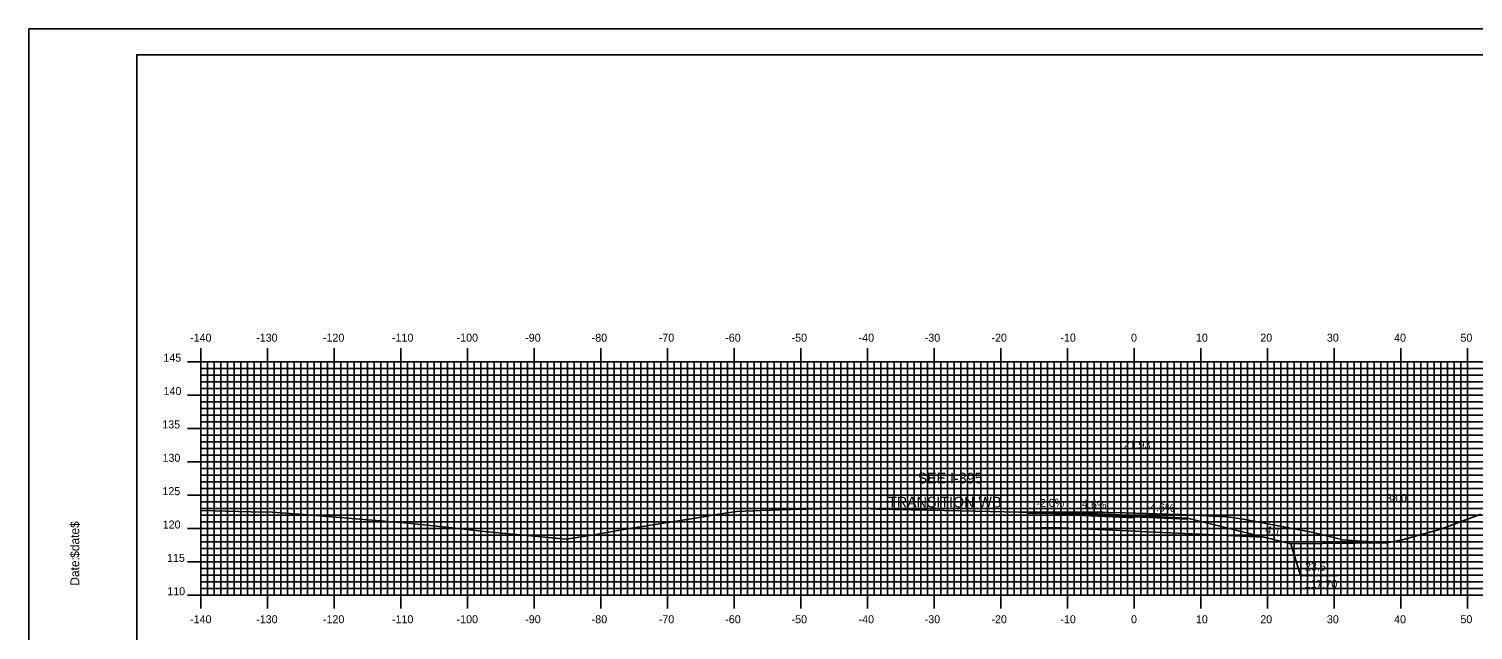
# Model space of a CAD drawing. Extents: x 853328 to 853671, y 364661 to 364881.
# Drawn here: x 853327.5 to 853544.1, y 364791.1 to 364881.3 of the extents above; entities that cross this region are included whole.
import ezdxf

# ---------------------------------------------------------------- set-up
doc = ezdxf.new("R2010")
doc.units = 0
for name, color, linetype in [('ANNOTATION', 7, 'Continuous'), ('BORDER', 7, 'Continuous'), ('D_Roadway_Centerline_Text', 7, 'Continuous'), ('D_Roadway_Edge_Shoulder', 7, 'Continuous'), ('D_Roadway_Edge_TW', 7, 'Continuous'), ('D_Roadway_Pavement', 7, 'Continuous'), ('D_Roadway_SubGrade', 7, 'Continuous'), ('D_Text_Standard', 7, 'Continuous'), ('H_V ANNOTATION', 7, 'Continuous'), ('M_Roadway_Centerline', 7, 'Continuous'), ('MAJOR', 7, 'Continuous'), ('MINOR', 7, 'Continuous'), ('PLOT BOUNDARY', 7, 'Continuous'), ('S_Roadway_Centerline', 7, 'Continuous')]:
    doc.layers.add(name, color=color, linetype=linetype)

msp = doc.modelspace()

# ---------------------------------------------------------------- linework, layer by layer
at = {"layer": 'ANNOTATION'}
for points in [[(853512.79, 364805.07), (853516.79, 364804.07), (853531.25, 364804.2)], [(853523.9, 364799.34), (853518.21, 364799.34), (853516.79, 364804.07)]]:
    msp.add_lwpolyline(points, dxfattribs=at)
at = {"layer": 'BORDER'}
msp.add_lwpolyline([(853343.69, 364667.37), (853663.69, 364667.37), (853663.69, 364877.37), (853343.69, 364877.37)], close=True, dxfattribs=at)
at = {"layer": 'D_Roadway_Edge_Shoulder'}
for points in [[(853481.29, 364808.86), (853477.29, 364808.78), (853477.29, 364808.61), (853481.29, 364808.68)], [(853493.29, 364808.31), (853501.29, 364807.94), (853501.29, 364807.77), (853493.29, 364808.13)]]:
    msp.add_lwpolyline(points, close=True, dxfattribs=at)
at = {"layer": 'D_Roadway_Edge_TW'}
msp.add_lwpolyline([(853481.29, 364808.86), (853493.29, 364808.31), (853493.29, 364808.13), (853481.29, 364808.68)], close=True, dxfattribs=at)
at = {"layer": 'D_Roadway_Pavement'}
msp.add_lwpolyline([(853481.29, 364808.68), (853493.29, 364808.13), (853493.29, 364807.96), (853481.29, 364808.51)], close=True, dxfattribs=at)
for points in [[(853481.29, 364808.68), (853481.29, 364808.51)], [(853493.29, 364808.13), (853493.29, 364807.96)], [(853493.29, 364808.13), (853493.29, 364807.96)]]:
    msp.add_lwpolyline(points, dxfattribs=at)
at = {"layer": 'D_Roadway_SubGrade'}
msp.add_line((853477.29, 364806.43), (853477.29, 364816.24), dxfattribs=at)
for points in [[(853481.29, 364806.51), (853477.29, 364806.43), (853477.29, 364808.78), (853477.29, 364808.61), (853481.29, 364808.68), (853481.29, 364808.51)], [(853481.29, 364808.51), (853493.29, 364807.96), (853493.29, 364805.96), (853481.29, 364806.51)], [(853493.29, 364807.96), (853493.29, 364808.13), (853501.29, 364807.77), (853501.29, 364807.94), (853512.79, 364805.07), (853493.29, 364805.96)]]:
    msp.add_lwpolyline(points, close=True, dxfattribs=at)
at = {"layer": 'MAJOR'}
for p, q in [((853353.29, 364833.38), (853353.29, 364831.37)), ((853363.29, 364833.38), (853363.29, 364831.37)), ((853373.29, 364833.38), (853373.29, 364831.37)), ((853383.29, 364833.38), (853383.29, 364831.37)), ((853393.29, 364833.38), (853393.29, 364831.37)), ((853403.29, 364833.38), (853403.29, 364831.37)), ((853413.29, 364833.38), (853413.29, 364831.37)), ((853423.29, 364833.38), (853423.29, 364831.37)), ((853433.29, 364833.38), (853433.29, 364831.37)), ((853443.29, 364833.38), (853443.29, 364831.37)), ((853453.29, 364833.38), (853453.29, 364831.37)), ((853463.29, 364833.38), (853463.29, 364831.37)), ((853473.29, 364833.38), (853473.29, 364831.37)), ((853483.29, 364833.38), (853483.29, 364831.37)), ((853493.29, 364833.38), (853493.29, 364831.37)), ((853503.29, 364833.38), (853503.29, 364831.37)), ((853513.29, 364833.38), (853513.29, 364831.37)), ((853523.29, 364833.38), (853523.29, 364831.37)), ((853533.29, 364833.38), (853533.29, 364831.37)), ((853543.29, 364833.38), (853543.29, 364831.37)), ((853351.29, 364831.37), (853353.29, 364831.37)), ((853353.29, 364831.37), (853633.29, 364831.37)), ((853353.29, 364796.37), (853353.29, 364831.37)), ((853353.29, 364796.37), (853353.29, 364831.37)), ((853353.29, 364831.37), (853633.29, 364831.37)), ((853363.29, 364796.37), (853363.29, 364831.37)), ((853373.29, 364796.37), (853373.29, 364831.37)), ((853383.29, 364796.37), (853383.29, 364831.37)), ((853393.29, 364796.37), (853393.29, 364831.37)), ((853403.29, 364796.37), (853403.29, 364831.37)), ((853413.29, 364796.37), (853413.29, 364831.37)), ((853423.29, 364796.37), (853423.29, 364831.37)), ((853433.29, 364796.37), (853433.29, 364831.37)), ((853443.29, 364796.37), (853443.29, 364831.37)), ((853453.29, 364796.37), (853453.29, 364831.37)), ((853463.29, 364796.37), (853463.29, 364831.37)), ((853473.29, 364796.37), (853473.29, 364831.37)), ((853483.29, 364796.37), (853483.29, 364831.37)), ((853493.29, 364796.37), (853493.29, 364831.37)), ((853503.29, 364796.37), (853503.29, 364831.37)), ((853513.29, 364796.37), (853513.29, 364831.37)), ((853523.29, 364796.37), (853523.29, 364831.37)), ((853533.29, 364796.37), (853533.29, 364831.37)), ((853543.29, 364796.37), (853543.29, 364831.37)), ((853351.29, 364826.37), (853353.29, 364826.37)), ((853353.29, 364826.37), (853633.29, 364826.37)), ((853351.29, 364821.37), (853353.29, 364821.37)), ((853353.29, 364821.37), (853633.29, 364821.37)), ((853351.29, 364816.37), (853353.29, 364816.37)), ((853353.29, 364816.37), (853633.29, 364816.37)), ((853351.29, 364811.37), (853353.29, 364811.37)), ((853353.29, 364811.37), (853633.29, 364811.37)), ((853351.29, 364806.37), (853353.29, 364806.37)), ((853353.29, 364806.37), (853633.29, 364806.37)), ((853351.29, 364801.37), (853353.29, 364801.37)), ((853353.29, 364801.37), (853633.29, 364801.37)), ((853351.29, 364796.37), (853353.29, 364796.37)), ((853353.29, 364796.37), (853633.29, 364796.37)), ((853353.29, 364796.37), (853633.29, 364796.37)), ((853353.29, 364794.37), (853353.29, 364796.37)), ((853363.29, 364794.37), (853363.29, 364796.37)), ((853373.29, 364794.37), (853373.29, 364796.37)), ((853383.29, 364794.37), (853383.29, 364796.37)), ((853393.29, 364794.37), (853393.29, 364796.37)), ((853403.29, 364794.37), (853403.29, 364796.37)), ((853413.29, 364794.37), (853413.29, 364796.37)), ((853423.29, 364794.37), (853423.29, 364796.37)), ((853433.29, 364794.37), (853433.29, 364796.37)), ((853443.29, 364794.37), (853443.29, 364796.37)), ((853453.29, 364794.37), (853453.29, 364796.37)), ((853463.29, 364794.37), (853463.29, 364796.37)), ((853473.29, 364794.37), (853473.29, 364796.37)), ((853483.29, 364794.37), (853483.29, 364796.37)), ((853493.29, 364794.37), (853493.29, 364796.37)), ((853503.29, 364794.37), (853503.29, 364796.37)), ((853513.29, 364794.37), (853513.29, 364796.37)), ((853523.29, 364794.37), (853523.29, 364796.37)), ((853533.29, 364794.37), (853533.29, 364796.37)), ((853543.29, 364794.37), (853543.29, 364796.37))]:
    msp.add_line(p, q, dxfattribs=at)
at = {"layer": 'MINOR'}
for p, q in [((853353.29, 364830.37), (853633.29, 364830.37)), ((853353.29, 364830.37), (853355.3, 364830.37)), ((853354.29, 364796.37), (853354.29, 364831.37)), ((853355.29, 364796.37), (853355.29, 364831.37)), ((853356.29, 364796.37), (853356.29, 364831.37)), ((853357.29, 364796.37), (853357.29, 364831.37)), ((853358.29, 364796.37), (853358.29, 364831.37)), ((853359.29, 364796.37), (853359.29, 364831.37)), ((853360.29, 364796.37), (853360.29, 364831.37)), ((853361.29, 364796.37), (853361.29, 364831.37)), ((853362.29, 364796.37), (853362.29, 364831.37)), ((853364.29, 364796.37), (853364.29, 364831.37)), ((853365.29, 364796.37), (853365.29, 364831.37)), ((853366.29, 364796.37), (853366.29, 364831.37)), ((853367.29, 364796.37), (853367.29, 364831.37)), ((853368.29, 364796.37), (853368.29, 364831.37)), ((853369.29, 364796.37), (853369.29, 364831.37)), ((853370.29, 364796.37), (853370.29, 364831.37)), ((853371.29, 364796.37), (853371.29, 364831.37)), ((853372.29, 364796.37), (853372.29, 364831.37)), ((853374.29, 364796.37), (853374.29, 364831.37)), ((853375.29, 364796.37), (853375.29, 364831.37)), ((853376.29, 364796.37), (853376.29, 364831.37)), ((853377.29, 364796.37), (853377.29, 364831.37)), ((853378.29, 364796.37), (853378.29, 364831.37)), ((853379.29, 364796.37), (853379.29, 364831.37)), ((853380.29, 364796.37), (853380.29, 364831.37)), ((853381.29, 364796.37), (853381.29, 364831.37)), ((853382.29, 364796.37), (853382.29, 364831.37)), ((853384.29, 364796.37), (853384.29, 364831.37)), ((853385.29, 364796.37), (853385.29, 364831.37)), ((853386.29, 364796.37), (853386.29, 364831.37)), ((853387.29, 364796.37), (853387.29, 364831.37)), ((853388.29, 364796.37), (853388.29, 364831.37)), ((853389.29, 364796.37), (853389.29, 364831.37)), ((853390.29, 364796.37), (853390.29, 364831.37)), ((853391.29, 364796.37), (853391.29, 364831.37)), ((853392.29, 364796.37), (853392.29, 364831.37)), ((853394.29, 364796.37), (853394.29, 364831.37)), ((853395.29, 364796.37), (853395.29, 364831.37)), ((853396.29, 364796.37), (853396.29, 364831.37)), ((853397.29, 364796.37), (853397.29, 364831.37)), ((853398.29, 364796.37), (853398.29, 364831.37)), ((853399.29, 364796.37), (853399.29, 364831.37)), ((853400.29, 364796.37), (853400.29, 364831.37)), ((853401.29, 364796.37), (853401.29, 364831.37)), ((853402.29, 364796.37), (853402.29, 364831.37)), ((853404.29, 364796.37), (853404.29, 364831.37)), ((853405.29, 364796.37), (853405.29, 364831.37)), ((853406.29, 364796.37), (853406.29, 364831.37)), ((853407.29, 364796.37), (853407.29, 364831.37)), ((853408.29, 364796.37), (853408.29, 364831.37)), ((853409.29, 364796.37), (853409.29, 364831.37)), ((853410.29, 364796.37), (853410.29, 364831.37)), ((853411.29, 364796.37), (853411.29, 364831.37)), ((853412.29, 364796.37), (853412.29, 364831.37)), ((853414.29, 364796.37), (853414.29, 364831.37)), ((853415.29, 364796.37), (853415.29, 364831.37)), ((853416.29, 364796.37), (853416.29, 364831.37)), ((853417.29, 364796.37), (853417.29, 364831.37)), ((853418.29, 364796.37), (853418.29, 364831.37)), ((853419.29, 364796.37), (853419.29, 364831.37)), ((853420.29, 364796.37), (853420.29, 364831.37)), ((853421.29, 364796.37), (853421.29, 364831.37)), ((853422.29, 364796.37), (853422.29, 364831.37)), ((853424.29, 364796.37), (853424.29, 364831.37)), ((853425.29, 364796.37), (853425.29, 364831.37)), ((853426.29, 364796.37), (853426.29, 364831.37)), ((853427.29, 364796.37), (853427.29, 364831.37)), ((853428.29, 364796.37), (853428.29, 364831.37)), ((853429.29, 364796.37), (853429.29, 364831.37)), ((853430.29, 364796.37), (853430.29, 364831.37)), ((853431.29, 364796.37), (853431.29, 364831.37)), ((853432.29, 364796.37), (853432.29, 364831.37)), ((853434.29, 364796.37), (853434.29, 364831.37)), ((853435.29, 364796.37), (853435.29, 364831.37)), ((853436.29, 364796.37), (853436.29, 364831.37)), ((853437.29, 364796.37), (853437.29, 364831.37)), ((853438.29, 364796.37), (853438.29, 364831.37)), ((853439.29, 364796.37), (853439.29, 364831.37)), ((853440.29, 364796.37), (853440.29, 364831.37)), ((853441.29, 364796.37), (853441.29, 364831.37)), ((853442.29, 364796.37), (853442.29, 364831.37)), ((853444.29, 364796.37), (853444.29, 364831.37)), ((853445.29, 364796.37), (853445.29, 364831.37)), ((853446.29, 364796.37), (853446.29, 364831.37)), ((853447.29, 364796.37), (853447.29, 364831.37)), ((853448.29, 364796.37), (853448.29, 364831.37)), ((853449.29, 364796.37), (853449.29, 364831.37)), ((853450.29, 364796.37), (853450.29, 364831.37)), ((853451.29, 364796.37), (853451.29, 364831.37)), ((853452.29, 364796.37), (853452.29, 364831.37)), ((853454.29, 364796.37), (853454.29, 364831.37)), ((853455.29, 364796.37), (853455.29, 364831.37)), ((853456.29, 364796.37), (853456.29, 364831.37)), ((853457.29, 364796.37), (853457.29, 364831.37)), ((853458.29, 364796.37), (853458.29, 364831.37)), ((853459.29, 364796.37), (853459.29, 364831.37)), ((853460.29, 364796.37), (853460.29, 364831.37)), ((853461.29, 364796.37), (853461.29, 364831.37)), ((853462.29, 364796.37), (853462.29, 364831.37)), ((853464.29, 364796.37), (853464.29, 364831.37)), ((853465.29, 364796.37), (853465.29, 364831.37)), ((853466.29, 364796.37), (853466.29, 364831.37)), ((853467.29, 364796.37), (853467.29, 364831.37)), ((853468.29, 364796.37), (853468.29, 364831.37)), ((853469.29, 364796.37), (853469.29, 364831.37)), ((853470.29, 364796.37), (853470.29, 364831.37)), ((853471.29, 364796.37), (853471.29, 364831.37)), ((853472.29, 364796.37), (853472.29, 364831.37)), ((853474.29, 364796.37), (853474.29, 364831.37)), ((853475.29, 364796.37), (853475.29, 364831.37)), ((853476.29, 364796.37), (853476.29, 364831.37)), ((853477.29, 364796.37), (853477.29, 364831.37)), ((853478.29, 364796.37), (853478.29, 364831.37)), ((853479.29, 364796.37), (853479.29, 364831.37)), ((853480.29, 364796.37), (853480.29, 364831.37)), ((853481.29, 364796.37), (853481.29, 364831.37)), ((853482.29, 364796.37), (853482.29, 364831.37)), ((853484.29, 364796.37), (853484.29, 364831.37)), ((853485.29, 364796.37), (853485.29, 364831.37)), ((853486.29, 364796.37), (853486.29, 364831.37)), ((853487.29, 364796.37), (853487.29, 364831.37)), ((853488.29, 364796.37), (853488.29, 364831.37)), ((853489.29, 364796.37), (853489.29, 364831.37)), ((853490.29, 364796.37), (853490.29, 364831.37)), ((853491.29, 364796.37), (853491.29, 364831.37)), ((853492.29, 364796.37), (853492.29, 364831.37)), ((853494.29, 364796.37), (853494.29, 364831.37)), ((853495.29, 364796.37), (853495.29, 364831.37)), ((853496.29, 364796.37), (853496.29, 364831.37)), ((853497.29, 364796.37), (853497.29, 364831.37)), ((853498.29, 364796.37), (853498.29, 364831.37)), ((853499.29, 364796.37), (853499.29, 364831.37)), ((853500.29, 364796.37), (853500.29, 364831.37)), ((853501.29, 364796.37), (853501.29, 364831.37)), ((853502.29, 364796.37), (853502.29, 364831.37)), ((853504.29, 364796.37), (853504.29, 364831.37)), ((853505.29, 364796.37), (853505.29, 364831.37)), ((853506.29, 364796.37), (853506.29, 364831.37)), ((853507.29, 364796.37), (853507.29, 364831.37)), ((853508.29, 364796.37), (853508.29, 364831.37)), ((853509.29, 364796.37), (853509.29, 364831.37)), ((853510.29, 364796.37), (853510.29, 364831.37)), ((853511.29, 364796.37), (853511.29, 364831.37)), ((853512.29, 364796.37), (853512.29, 364831.37)), ((853514.29, 364796.37), (853514.29, 364831.37)), ((853515.29, 364796.37), (853515.29, 364831.37)), ((853516.29, 364796.37), (853516.29, 364831.37)), ((853517.29, 364796.37), (853517.29, 364831.37)), ((853518.29, 364796.37), (853518.29, 364831.37)), ((853519.29, 364796.37), (853519.29, 364831.37)), ((853520.29, 364796.37), (853520.29, 364831.37)), ((853521.29, 364796.37), (853521.29, 364831.37)), ((853522.29, 364796.37), (853522.29, 364831.37)), ((853524.29, 364796.37), (853524.29, 364831.37)), ((853525.29, 364796.37), (853525.29, 364831.37)), ((853526.29, 364796.37), (853526.29, 364831.37)), ((853527.29, 364796.37), (853527.29, 364831.37)), ((853528.29, 364796.37), (853528.29, 364831.37)), ((853529.29, 364796.37), (853529.29, 364831.37)), ((853530.29, 364796.37), (853530.29, 364831.37)), ((853531.29, 364796.37), (853531.29, 364831.37)), ((853532.29, 364796.37), (853532.29, 364831.37)), ((853534.29, 364796.37), (853534.29, 364831.37)), ((853535.29, 364796.37), (853535.29, 364831.37)), ((853536.29, 364796.37), (853536.29, 364831.37)), ((853537.29, 364796.37), (853537.29, 364831.37)), ((853538.29, 364796.37), (853538.29, 364831.37)), ((853539.29, 364796.37), (853539.29, 364831.37)), ((853540.29, 364796.37), (853540.29, 364831.37)), ((853541.29, 364796.37), (853541.29, 364831.37)), ((853542.29, 364796.37), (853542.29, 364831.37)), ((853353.29, 364829.37), (853633.29, 364829.37)), ((853353.29, 364829.37), (853355.3, 364829.37)), ((853353.29, 364828.37), (853633.29, 364828.37)), ((853353.29, 364828.37), (853355.3, 364828.37)), ((853353.29, 364827.37), (853633.29, 364827.37)), ((853353.29, 364827.37), (853355.3, 364827.37)), ((853353.29, 364825.37), (853633.29, 364825.37)), ((853353.29, 364825.37), (853355.3, 364825.37)), ((853353.29, 364824.37), (853633.29, 364824.37)), ((853353.29, 364824.37), (853355.3, 364824.37)), ((853353.29, 364823.37), (853633.29, 364823.37)), ((853353.29, 364823.37), (853355.3, 364823.37)), ((853353.29, 364822.37), (853633.29, 364822.37)), ((853353.29, 364822.37), (853355.3, 364822.37)), ((853353.29, 364820.37), (853633.29, 364820.37)), ((853353.29, 364820.37), (853355.3, 364820.37)), ((853353.29, 364819.37), (853633.29, 364819.37)), ((853353.29, 364819.37), (853355.3, 364819.37)), ((853353.29, 364818.37), (853633.29, 364818.37)), ((853353.29, 364818.37), (853355.3, 364818.37)), ((853353.29, 364817.37), (853633.29, 364817.37)), ((853353.29, 364817.37), (853355.3, 364817.37)), ((853353.29, 364815.37), (853633.29, 364815.37)), ((853353.29, 364815.37), (853355.3, 364815.37)), ((853353.29, 364814.37), (853633.29, 364814.37)), ((853353.29, 364814.37), (853355.3, 364814.37)), ((853353.29, 364813.37), (853633.29, 364813.37)), ((853353.29, 364813.37), (853355.3, 364813.37)), ((853353.29, 364812.37), (853633.29, 364812.37)), ((853353.29, 364812.37), (853355.3, 364812.37)), ((853353.29, 364810.37), (853633.29, 364810.37)), ((853353.29, 364810.37), (853355.3, 364810.37)), ((853353.29, 364809.37), (853633.29, 364809.37)), ((853353.29, 364809.37), (853355.3, 364809.37)), ((853353.29, 364808.37), (853633.29, 364808.37)), ((853353.29, 364808.37), (853355.3, 364808.37)), ((853353.29, 364807.37), (853633.29, 364807.37)), ((853353.29, 364807.37), (853355.3, 364807.37)), ((853353.29, 364805.37), (853633.29, 364805.37)), ((853353.29, 364805.37), (853355.3, 364805.37)), ((853353.29, 364804.37), (853633.29, 364804.37)), ((853353.29, 364804.37), (853355.3, 364804.37)), ((853353.29, 364803.37), (853633.29, 364803.37)), ((853353.29, 364803.37), (853355.3, 364803.37)), ((853353.29, 364802.37), (853633.29, 364802.37)), ((853353.29, 364802.37), (853355.3, 364802.37)), ((853353.29, 364800.37), (853633.29, 364800.37)), ((853353.29, 364800.37), (853355.3, 364800.37)), ((853353.29, 364799.37), (853633.29, 364799.37)), ((853353.29, 364799.37), (853355.3, 364799.37)), ((853353.29, 364798.37), (853633.29, 364798.37)), ((853353.29, 364798.37), (853355.3, 364798.37)), ((853353.29, 364797.37), (853633.29, 364797.37)), ((853353.29, 364797.37), (853355.3, 364797.37))]:
    msp.add_line(p, q, dxfattribs=at)
at = {"layer": 'PLOT BOUNDARY'}
msp.add_lwpolyline([(853327.51, 364661.25), (853667.51, 364661.25), (853667.51, 364881.25), (853327.51, 364881.25)], close=True, dxfattribs=at)
at = {"layer": 'S_Roadway_Centerline'}
msp.add_lwpolyline([(853353.29, 364809.08), (853362.72, 364808.84), (853363.32, 364808.85), (853369.38, 364808.43), (853376.52, 364807.84), (853383.85, 364807.21), (853390.52, 364806.5), (853395.86, 364805.9), (853401.69, 364805.37), (853408.16, 364804.77), (853408.4, 364804.83), (853412.53, 364805.47), (853417.27, 364806.3), (853426.55, 364807.79), (853431.29, 364808.58), (853433.62, 364808.93), (853437.4, 364809.09), (853441.82, 364809.22), (853446.35, 364809.3), (853449.36, 364809.37), (853449.47, 364809.41), (853453.82, 364809.3), (853454.8, 364809.28), (853467.35, 364809), (853475.97, 364808.8), (853476.72, 364808.81), (853477.6, 364808.8), (853488.58, 364808.82), (853489.45, 364808.79), (853491.86, 364808.73), (853498.27, 364808.54), (853500.24, 364808.48), (853506.13, 364808.17), (853506.84, 364808.15), (853509.4, 364807.82), (853520.14, 364805.76), (853524.57, 364804.65), (853525.16, 364804.63), (853531.25, 364804.2), (853533.48, 364804.68), (853539.28, 364806.27), (853545.28, 364808.52)], dxfattribs=at)

# ---------------------------------------------------------------- texts
at = {"layer": 'ANNOTATION'}
for s, height, p in [('SEE I-395 ', 1.6, (853460.79, 364813.13)), ('TRANSITION WB', 1.6, (853456.38, 364809.53)), ("23.5' ", 1.2, (853518.9, 364800.07)), ('117.70', 1.2, (853518.84, 364797.47))]:
    msp.add_text(s, height=height, dxfattribs=at).set_placement(p)
for s, rotation, p in [('-2.0%', 1.1458, (853478.61, 364809.57)), ('4.6%', 357.3663, (853485.44, 364809.47)), ('-4.6%', 357.3663, (853495.12, 364809.03)), ('4:1', 345.9638, (853512.88, 364805.7))]:
    msp.add_text(s, height=1.2, rotation=rotation, dxfattribs=at).set_placement(p)
at = {"layer": 'BORDER'}
for s, p in [('$date$', (853335.06, 364801.98)), ('Date:', (853335.06, 364797.8))]:
    msp.add_text(s, height=1.339, rotation=90, dxfattribs=at).set_placement(p)
at = {"layer": 'D_Roadway_Centerline_Text'}
msp.add_text('121.93', height=1.2, dxfattribs=at).set_placement((853490.81, 364818.34))
at = {"layer": 'D_Text_Standard'}
msp.add_text("38.0'", height=1.2, dxfattribs=at).set_placement((853531.06, 364810.34))
at = {"layer": 'H_V ANNOTATION'}
for s, p in [('-140', (853351.68, 364834.37)), ('-130', (853361.6, 364834.37)), ('-120', (853371.61, 364834.37)), ('-110', (853381.96, 364834.37)), ('-100', (853391.66, 364834.37)), ('-90', (853401.95, 364834.37)), ('-80', (853411.92, 364834.37)), ('-70', (853421.98, 364834.37)), ('-60', (853431.95, 364834.37)), ('-50', (853441.9, 364834.37)), ('-40', (853451.95, 364834.37)), ('-30', (853461.87, 364834.37)), ('-20', (853471.88, 364834.37)), ('-10', (853482.22, 364834.37)), ('0', (853492.81, 364834.37)), ('10', (853502.55, 364834.37)), ('20', (853512.2, 364834.37)), ('30', (853522.19, 364834.37)), ('40', (853532.27, 364834.37)), ('50', (853542.22, 364834.37)), ('145', (853347.67, 364831.37)), ('140', (853347.7, 364826.37)), ('135', (853347.52, 364821.37)), ('130', (853347.55, 364816.37)), ('125', (853347.54, 364811.37)), ('120', (853347.58, 364806.37)), ('115', (853348.23, 364801.37)), ('110', (853348.26, 364796.37)), ('-140', (853351.68, 364792.17)), ('-130', (853361.6, 364792.17)), ('-120', (853371.61, 364792.17)), ('-110', (853381.96, 364792.17)), ('-100', (853391.66, 364792.17)), ('-90', (853401.95, 364792.17)), ('-80', (853411.92, 364792.17)), ('-70', (853421.98, 364792.17)), ('-60', (853431.95, 364792.17)), ('-50', (853441.9, 364792.17)), ('-40', (853451.95, 364792.17)), ('-30', (853461.87, 364792.17)), ('-20', (853471.88, 364792.17)), ('-10', (853482.22, 364792.17)), ('0', (853492.81, 364792.17)), ('10', (853502.55, 364792.17)), ('20', (853512.2, 364792.17)), ('30', (853522.19, 364792.17)), ('40', (853532.27, 364792.17)), ('50', (853542.22, 364792.17))]:
    msp.add_text(s, height=1.2, dxfattribs=at).set_placement(p)
at = {"layer": 'M_Roadway_Centerline'}
for s, p in [('C', (853449.47, 364809.41)), ('L', (853449.47, 364809.4)), ('C', (853491.86, 364808.73)), ('L', (853491.86, 364808.72))]:
    msp.add_text(s, height=0.0146, dxfattribs=at).set_placement(p)
at = {"layer": 'MAJOR'}
msp.add_text('-', height=0.012, dxfattribs=at).set_placement((853353.29, 364796.37))

doc.saveas('drawing.dxf')
